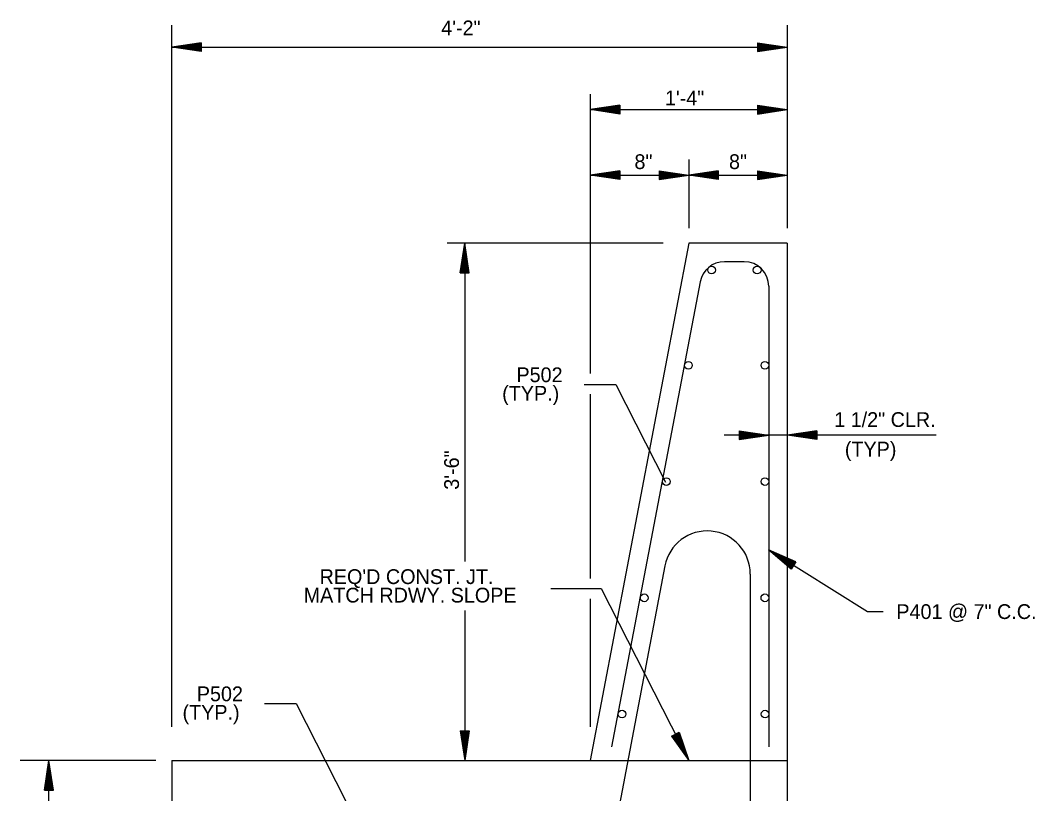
# Model space of a CAD drawing. Extents: x 714919 to 718439, y 1619644 to 1621844.
# Drawn here: x 717030 to 717717, y 1620814 to 1621337 of the extents above; entities that cross this region are included whole.
import ezdxf

# ---------------------------------------------------------------- set-up
doc = ezdxf.new("R2010")
doc.units = 0
doc.layers.add('R_Dimension', color=7, linetype='Continuous')
doc.layers.add('R_Draft', color=7, linetype='Continuous')

msp = doc.modelspace()

# ---------------------------------------------------------------- linework, layer by layer
at = {"layer": 'R_Dimension'}
for p, q in [((717152.81, 1621322.06), (717132.81, 1621319.06)), ((717152.81, 1621316.06), (717132.81, 1621319.06)), ((717152.81, 1621321.56), (717136.15, 1621319.06)), ((717152.81, 1621316.56), (717136.15, 1621319.06)), ((717152.81, 1621321.05), (717139.59, 1621319.06)), ((717152.81, 1621317.07), (717139.59, 1621319.06)), ((717152.81, 1621320.55), (717142.92, 1621319.06)), ((717152.81, 1621317.57), (717142.92, 1621319.06)), ((717152.81, 1621320.03), (717146.31, 1621319.06)), ((717152.81, 1621318.08), (717146.31, 1621319.06)), ((717152.81, 1621319.53), (717149.65, 1621319.06)), ((717152.81, 1621318.59), (717149.65, 1621319.06)), ((717152.81, 1621322.06), (717152.81, 1621316.06)), ((717529.48, 1621322.06), (717549.48, 1621319.06)), ((717529.48, 1621322.06), (717529.48, 1621316.06)), ((717529.48, 1621321.56), (717546.14, 1621319.06)), ((717529.48, 1621321.05), (717542.7, 1621319.06)), ((717529.48, 1621320.55), (717539.37, 1621319.06)), ((717529.48, 1621320.03), (717535.98, 1621319.06)), ((717529.48, 1621319.53), (717532.64, 1621319.06)), ((717529.48, 1621316.06), (717549.48, 1621319.06)), ((717529.48, 1621318.08), (717535.98, 1621319.06)), ((717529.48, 1621317.07), (717542.7, 1621319.06)), ((717529.48, 1621316.56), (717546.14, 1621319.06)), ((717529.48, 1621317.57), (717539.37, 1621319.06)), ((717529.48, 1621318.59), (717532.64, 1621319.06)), ((717436.14, 1621279.83), (717416.14, 1621276.83)), ((717436.14, 1621273.83), (717416.14, 1621276.83)), ((717436.14, 1621279.33), (717419.48, 1621276.83)), ((717436.14, 1621274.33), (717419.48, 1621276.83)), ((717436.14, 1621278.82), (717422.92, 1621276.83)), ((717436.14, 1621274.84), (717422.92, 1621276.83)), ((717436.14, 1621278.32), (717426.25, 1621276.83)), ((717436.14, 1621275.34), (717426.25, 1621276.83)), ((717436.14, 1621277.8), (717429.64, 1621276.83)), ((717436.14, 1621275.85), (717429.64, 1621276.83)), ((717436.14, 1621277.3), (717432.98, 1621276.83)), ((717436.14, 1621276.36), (717432.98, 1621276.83)), ((717436.14, 1621279.83), (717436.14, 1621273.83)), ((717529.48, 1621279.83), (717549.48, 1621276.83)), ((717529.48, 1621279.83), (717529.48, 1621273.83)), ((717529.48, 1621279.33), (717546.14, 1621276.83)), ((717529.48, 1621278.82), (717542.7, 1621276.83)), ((717529.48, 1621278.32), (717539.37, 1621276.83)), ((717529.48, 1621277.8), (717535.98, 1621276.83)), ((717529.48, 1621277.3), (717532.64, 1621276.83)), ((717529.48, 1621273.83), (717549.48, 1621276.83)), ((717529.48, 1621275.85), (717535.98, 1621276.83)), ((717529.48, 1621274.84), (717542.7, 1621276.83)), ((717529.48, 1621274.33), (717546.14, 1621276.83)), ((717529.48, 1621275.34), (717539.37, 1621276.83)), ((717529.48, 1621276.36), (717532.64, 1621276.83)), ((717436.14, 1621235.42), (717416.14, 1621232.42)), ((717436.14, 1621235.42), (717436.14, 1621229.42)), ((717462.81, 1621235.42), (717482.81, 1621232.42)), ((717462.81, 1621235.42), (717462.81, 1621229.42)), ((717502.81, 1621235.42), (717482.81, 1621232.42)), ((717502.81, 1621235.42), (717502.81, 1621229.42)), ((717529.48, 1621235.42), (717549.48, 1621232.42)), ((717529.48, 1621235.42), (717529.48, 1621229.42)), ((717436.14, 1621229.42), (717416.14, 1621232.42)), ((717436.14, 1621234.92), (717419.48, 1621232.42)), ((717436.14, 1621229.92), (717419.48, 1621232.42)), ((717436.14, 1621234.41), (717422.92, 1621232.42)), ((717436.14, 1621230.43), (717422.92, 1621232.42)), ((717436.14, 1621233.91), (717426.25, 1621232.42)), ((717436.14, 1621230.93), (717426.25, 1621232.42)), ((717436.14, 1621233.39), (717429.64, 1621232.42)), ((717436.14, 1621231.44), (717429.64, 1621232.42)), ((717436.14, 1621232.89), (717432.98, 1621232.42)), ((717436.14, 1621231.95), (717432.98, 1621232.42)), ((717462.81, 1621234.92), (717479.47, 1621232.42)), ((717462.81, 1621234.41), (717476.03, 1621232.42)), ((717462.81, 1621233.91), (717472.7, 1621232.42)), ((717462.81, 1621233.39), (717469.31, 1621232.42)), ((717462.81, 1621232.89), (717465.97, 1621232.42)), ((717462.81, 1621229.42), (717482.81, 1621232.42)), ((717462.81, 1621231.44), (717469.31, 1621232.42)), ((717462.81, 1621230.43), (717476.03, 1621232.42)), ((717462.81, 1621229.92), (717479.47, 1621232.42)), ((717462.81, 1621230.93), (717472.7, 1621232.42)), ((717462.81, 1621231.95), (717465.97, 1621232.42)), ((717502.81, 1621229.42), (717482.81, 1621232.42)), ((717502.81, 1621234.92), (717486.15, 1621232.42)), ((717502.81, 1621229.92), (717486.15, 1621232.42)), ((717502.81, 1621234.41), (717489.59, 1621232.42)), ((717502.81, 1621230.43), (717489.59, 1621232.42)), ((717502.81, 1621233.91), (717492.92, 1621232.42)), ((717502.81, 1621230.93), (717492.92, 1621232.42)), ((717502.81, 1621233.39), (717496.31, 1621232.42)), ((717502.81, 1621231.44), (717496.31, 1621232.42)), ((717502.81, 1621232.89), (717499.65, 1621232.42)), ((717502.81, 1621231.95), (717499.65, 1621232.42)), ((717529.48, 1621234.92), (717546.14, 1621232.42)), ((717529.48, 1621234.41), (717542.7, 1621232.42)), ((717529.48, 1621233.91), (717539.37, 1621232.42)), ((717529.48, 1621233.39), (717535.98, 1621232.42)), ((717529.48, 1621232.89), (717532.64, 1621232.42)), ((717529.48, 1621229.42), (717549.48, 1621232.42)), ((717529.48, 1621231.44), (717535.98, 1621232.42)), ((717529.48, 1621230.43), (717542.7, 1621232.42)), ((717529.48, 1621229.92), (717546.14, 1621232.42)), ((717529.48, 1621230.93), (717539.37, 1621232.42)), ((717529.48, 1621231.95), (717532.64, 1621232.42)), ((717328.17, 1621166.42), (717331.17, 1621186.42)), ((717328.67, 1621166.42), (717331.17, 1621183.08)), ((717334.17, 1621166.42), (717331.17, 1621186.42)), ((717333.67, 1621166.42), (717331.17, 1621183.08)), ((717329.18, 1621166.42), (717331.17, 1621179.64)), ((717329.68, 1621166.42), (717331.17, 1621176.31)), ((717333.16, 1621166.42), (717331.17, 1621179.64)), ((717332.66, 1621166.42), (717331.17, 1621176.31)), ((717330.2, 1621166.42), (717331.17, 1621172.92)), ((717330.7, 1621166.42), (717331.17, 1621169.58)), ((717332.15, 1621166.42), (717331.17, 1621172.92)), ((717331.64, 1621166.42), (717331.17, 1621169.58)), ((717328.17, 1621166.42), (717334.17, 1621166.42)), ((717516.98, 1621059.49), (717536.98, 1621056.49)), ((717516.98, 1621059.49), (717516.98, 1621053.49)), ((717516.98, 1621058.99), (717533.64, 1621056.49)), ((717516.98, 1621058.48), (717530.2, 1621056.49)), ((717516.98, 1621057.98), (717526.87, 1621056.49)), ((717516.98, 1621057.46), (717523.48, 1621056.49)), ((717516.98, 1621056.96), (717520.14, 1621056.49)), ((717569.48, 1621059.49), (717549.48, 1621056.49)), ((717569.48, 1621058.99), (717552.82, 1621056.49)), ((717569.48, 1621058.48), (717556.26, 1621056.49)), ((717569.48, 1621057.98), (717559.59, 1621056.49)), ((717569.48, 1621057.46), (717562.98, 1621056.49)), ((717569.48, 1621056.96), (717566.32, 1621056.49)), ((717569.48, 1621059.49), (717569.48, 1621053.49)), ((717516.98, 1621053.49), (717536.98, 1621056.49)), ((717516.98, 1621055.51), (717523.48, 1621056.49)), ((717516.98, 1621054.5), (717530.2, 1621056.49)), ((717516.98, 1621053.99), (717533.64, 1621056.49)), ((717516.98, 1621055), (717526.87, 1621056.49)), ((717516.98, 1621056.02), (717520.14, 1621056.49)), ((717569.48, 1621053.49), (717549.48, 1621056.49)), ((717569.48, 1621053.99), (717552.82, 1621056.49)), ((717569.48, 1621054.5), (717556.26, 1621056.49)), ((717569.48, 1621055), (717559.59, 1621056.49)), ((717569.48, 1621055.51), (717562.98, 1621056.49)), ((717569.48, 1621056.02), (717566.32, 1621056.49)), ((717555.38, 1620970.84), (717536.83, 1620978.9)), ((717552.2, 1620965.75), (717536.83, 1620978.9)), ((717555.11, 1620970.42), (717539.66, 1620977.13)), ((717552.46, 1620966.18), (717539.66, 1620977.13)), ((717552.73, 1620966.61), (717542.58, 1620975.3)), ((717554.84, 1620969.99), (717542.58, 1620975.3)), ((717554.58, 1620969.56), (717545.4, 1620973.54)), ((717553, 1620967.04), (717545.4, 1620973.54)), ((717553.27, 1620967.47), (717548.28, 1620971.74)), ((717554.3, 1620969.12), (717548.28, 1620971.74)), ((717553.54, 1620967.9), (717551.11, 1620969.97)), ((717554.04, 1620968.7), (717551.11, 1620969.97)), ((717555.38, 1620970.84), (717552.2, 1620965.75)), ((717328.17, 1620856.42), (717331.17, 1620836.42)), ((717328.17, 1620856.42), (717334.17, 1620856.42)), ((717328.67, 1620856.42), (717331.17, 1620839.76)), ((717329.18, 1620856.42), (717331.17, 1620843.2)), ((717329.68, 1620856.42), (717331.17, 1620846.53)), ((717330.2, 1620856.42), (717331.17, 1620849.92)), ((717330.7, 1620856.42), (717331.17, 1620853.26)), ((717334.17, 1620856.42), (717331.17, 1620836.42)), ((717332.15, 1620856.42), (717331.17, 1620849.92)), ((717333.16, 1620856.42), (717331.17, 1620843.2)), ((717333.67, 1620856.42), (717331.17, 1620839.76)), ((717332.66, 1620856.42), (717331.17, 1620846.53)), ((717331.64, 1620856.42), (717331.17, 1620853.26)), ((717471.04, 1620852.86), (717476.39, 1620855.59)), ((717471.04, 1620852.86), (717482.81, 1620836.42)), ((717471.49, 1620853.09), (717481.29, 1620839.39)), ((717471.94, 1620853.32), (717479.73, 1620842.45)), ((717472.39, 1620853.55), (717478.21, 1620845.42)), ((717472.85, 1620853.79), (717476.67, 1620848.44)), ((717473.3, 1620854.01), (717475.15, 1620851.41)), ((717474.13, 1620854.44), (717475.15, 1620851.41)), ((717474.59, 1620854.67), (717476.67, 1620848.44)), ((717475.04, 1620854.91), (717478.21, 1620845.42)), ((717475.49, 1620855.13), (717479.73, 1620842.45)), ((717475.94, 1620855.37), (717481.29, 1620839.39)), ((717476.39, 1620855.59), (717482.81, 1620836.42)), ((717046.74, 1620816.42), (717049.74, 1620836.42)), ((717047.24, 1620816.42), (717049.74, 1620833.08)), ((717052.74, 1620816.42), (717049.74, 1620836.42)), ((717052.24, 1620816.42), (717049.74, 1620833.08)), ((717047.75, 1620816.42), (717049.74, 1620829.64)), ((717048.25, 1620816.42), (717049.74, 1620826.31)), ((717051.73, 1620816.42), (717049.74, 1620829.64)), ((717051.23, 1620816.42), (717049.74, 1620826.31)), ((717046.74, 1620816.42), (717052.74, 1620816.42)), ((717048.77, 1620816.42), (717049.74, 1620822.92)), ((717049.27, 1620816.42), (717049.74, 1620819.58)), ((717050.72, 1620816.42), (717049.74, 1620822.92)), ((717050.21, 1620816.42), (717049.74, 1620819.58))]:
    msp.add_line(p, q, dxfattribs=at)
at = {"layer": 'R_Draft'}
for p, q in [((717132.81, 1620859.21), (717132.81, 1621333.85)), ((717549.48, 1621333.85), (717549.48, 1621196.58)), ((717132.81, 1621319.06), (717549.48, 1621319.06)), ((717416.14, 1621287.32), (717416.14, 1621098.28)), ((717416.14, 1621276.83), (717549.48, 1621276.83)), ((717482.81, 1621243.17), (717482.81, 1621196.58)), ((717416.14, 1621232.42), (717482.81, 1621232.42)), ((717482.81, 1621232.42), (717549.48, 1621232.42)), ((717465.49, 1621186.42), (717319.39, 1621186.42)), ((717331.17, 1621186.42), (717331.17, 1620971.12)), ((717482.81, 1621186.42), (717416.14, 1620836.42)), ((717549.48, 1621186.42), (717482.81, 1621186.42)), ((717482.81, 1621186.42), (717482.81, 1621186.42)), ((717549.48, 1621186.42), (717549.48, 1620736.42)), ((717520.31, 1621173.92), (717506.94, 1621173.92)), ((717490.57, 1621160.37), (717430.63, 1620845.67)), ((717536.98, 1621157.25), (717536.98, 1620845.67)), ((717416.14, 1621084.18), (717416.14, 1620959.44)), ((717650.29, 1621056.49), (717506.79, 1621056.49)), ((717466.66, 1620968.01), (717424.92, 1620748.92)), ((717524.48, 1620962.55), (717524.48, 1620783.94)), ((717416.14, 1620945.74), (717416.14, 1620859.21)), ((717331.17, 1620937.89), (717331.17, 1620836.42)), ((717122.02, 1620836.42), (717030.32, 1620836.42)), ((717049.74, 1620736.42), (717049.74, 1620836.42)), ((717132.81, 1620836.42), (717416.14, 1620836.42)), ((717132.81, 1620836.42), (717132.81, 1620636.42)), ((717416.14, 1620836.42), (717549.48, 1620836.42))]:
    msp.add_line(p, q, dxfattribs=at)
for points in [[(717412.01, 1621090.81), (717433.39, 1621090.81)], [(717433.39, 1621090.81), (717467.14, 1621024.7)], [(717614.5, 1620936.97), (717603.93, 1620936.97), (717536.83, 1620978.9)], [(717389.55, 1620952.66), (717423.46, 1620952.66), (717482.81, 1620836.42)], [(717195.64, 1620874.91), (717217.03, 1620874.91)], [(717217.03, 1620874.91), (717250.78, 1620808.81)]]:
    msp.add_lwpolyline(points, dxfattribs=at)
for centre in [(717498.29, 1621168.26), (717529.14, 1621168.26), (717482.63, 1621103.8), (717534.4, 1621103.8), (717467.64, 1621025.13), (717534.37, 1621025.13), (717452.66, 1620946.45), (717534.35, 1620946.45), (717437.67, 1620867.78), (717534.49, 1620867.78)]:
    msp.add_circle(centre, 2.6, dxfattribs=at)
for centre, radius, start, end in [((717506.94, 1621157.25), 16.67, 90, 169.2157), ((717520.31, 1621157.25), 16.67, 0, 90), ((717495.31, 1620962.55), 29.17, 360, 169.2157)]:
    msp.add_arc(centre, radius, start, end, dxfattribs=at)

# ---------------------------------------------------------------- texts
for s, p in [('4\'-2"', (717315.27, 1621327.11)), ('1\'-4"', (717466.71, 1621279.66)), ('8"', (717446.08, 1621236.59)), ('8"', (717510.09, 1621236.59)), ('P502', (717366.19, 1621092.39)), ('(TYP.)', (717356.52, 1621079.87)), ('1 1/2" CLR.', (717581.3, 1621062.08)), ('(TYP)', (717588.5, 1621042.08)), ("REQ'D CONST. JT.", (717232.92, 1620955.8)), ('MATCH RDWY. SLOPE', (717222.14, 1620943.28)), ('P401 @ 7" C.C.', (717623.37, 1620932.13)), ('P502', (717149.82, 1620876.49)), ('(TYP.)', (717140.15, 1620863.97))]:
    msp.add_text(s, height=10, dxfattribs=at).set_placement(p)
msp.add_text('3\'-6"', height=10, rotation=90, dxfattribs=at).set_placement((717327.28, 1621019.6))

doc.saveas('drawing.dxf')
